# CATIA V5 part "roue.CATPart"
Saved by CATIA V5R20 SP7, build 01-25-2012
Part number: roue
Bounding box of the stored display mesh (mm): x -350 to 350, y -349.95 to 349.95, z -40 to 40
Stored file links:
  U:\IAO\thinkmotion catia2\roue.CATPart
  U:\IAO\thinkmotion catia2\Ass_862_adubourgno.CATProduct
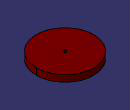
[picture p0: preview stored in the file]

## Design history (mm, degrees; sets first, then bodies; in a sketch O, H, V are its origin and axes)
Set1
  Point1 "H": linked copy from another document
Body1 (main body)
  Sketch1 on xy-plane, origin (0, 0, 0), H (1, 0, 0), V (0, 1, 0)
    circle A1 centre (0, 0) radius 20
    point P1 (0, 0)
    reference projected point E1 (0, 0) from Point1
    circle A2 centre (0, 0) radius 350
    point P2 (0, 0)
    reference projected point E2 (0, 0) from Point1
    radius A1 = 20
    distance E1 P1 = 0
    distance E2 P2 = 0
    radius A2 = 350
  Pad1: profile Sketch1, direction (0, 0, 1), length 40, mirrored extent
